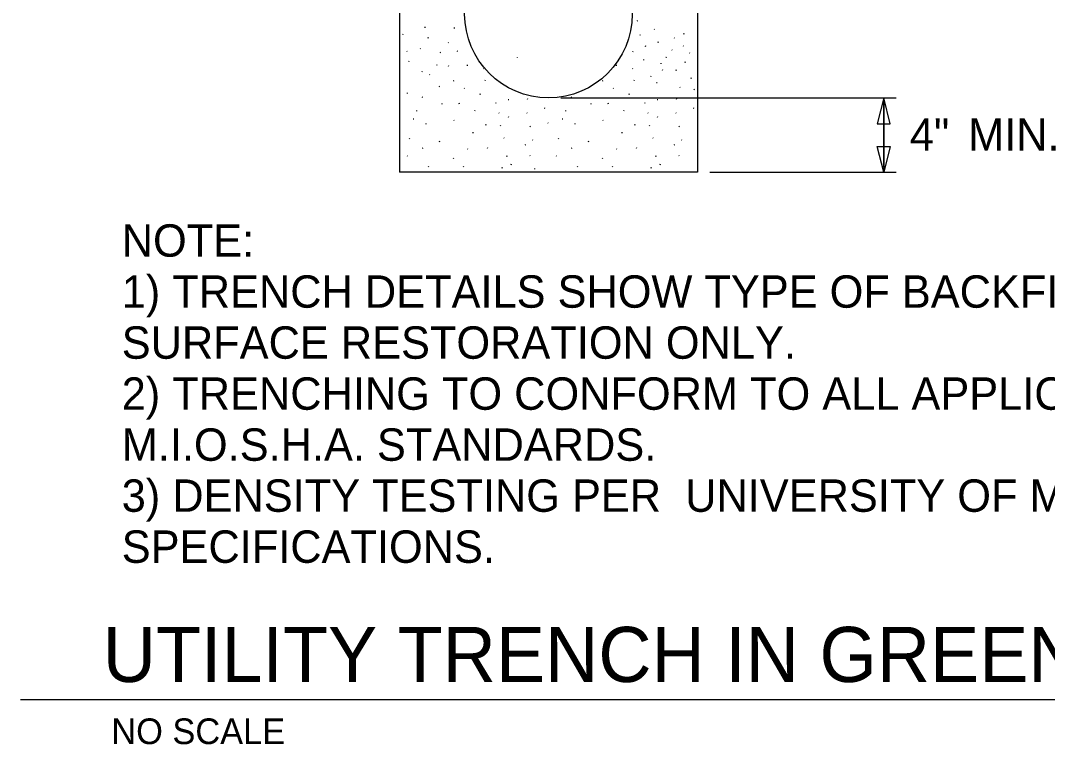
# Model space of a CAD drawing. Extents: x 9886.8 to 9948.5, y 10012 to 10070.9.
# Drawn here: x 9887.19 to 9920.27, y 10013.14 to 10036.46 of the extents above; entities that cross this region are included whole.
import ezdxf

# ---------------------------------------------------------------- set-up
doc = ezdxf.new("R2010")
doc.units = 0
for name, color, linetype in [('Default', 7, 'Continuous'), ('G-ANNO-TEXT', 7, 'Continuous'), ('G-ANNO-TTXT', 7, 'Continuous'), ('G-DETL-OTLN', 7, 'Continuous'), ('G-DETL-PATT', 7, 'Continuous')]:
    doc.layers.add(name, color=color, linetype=linetype)

# ---------------------------------------------------------------- blocks, each defined once
blk = doc.blocks.new('TERARR')
at = {"layer": 'Default'}
blk.add_lwpolyline([(-0.667, 0.167), (0, 0), (-0.667, -0.167)], close=True, dxfattribs=at)

msp = doc.modelspace()

# ---------------------------------------------------------------- linework, layer by layer
at = {"layer": 'Default'}
for p, q in [((9903.188, 10035.279), (9903.193, 10035.273)), ((9902.114, 10034.907), (9902.102, 10034.92)), ((9909.012, 10034.799), (9909.012, 10034.799)), ((9900.149, 10033.979), (9900.136, 10033.991)), ((9904.949, 10033.979), (9904.936, 10033.991)), ((9887.192, 10014.582), (9918.456, 10014.582))]:
    msp.add_line(p, q, dxfattribs=at)
at = {"layer": 'G-ANNO-TEXT'}
for p, q in [((9904.599, 10033.972), (9915.399, 10033.972)), ((9914.999, 10033.972), (9914.999, 10031.572)), ((9914.999, 10031.753), (9914.999, 10033.972)), ((9909.399, 10031.572), (9915.399, 10031.572)), ((9887.192, 10014.582), (9930.582, 10014.582))]:
    msp.add_line(p, q, dxfattribs=at)
at = {"layer": 'G-DETL-OTLN'}
for p, q in [((9899.399, 10039.372), (9899.399, 10031.572)), ((9908.999, 10039.372), (9908.999, 10031.572)), ((9908.999, 10031.572), (9899.399, 10031.572))]:
    msp.add_line(p, q, dxfattribs=at)
msp.add_circle((9904.199, 10036.672), 2.7, dxfattribs=at)
at = {"layer": 'G-DETL-PATT'}
for p, q in [((9900.237, 10036.24), (9900.211, 10036.235)), ((9901.179, 10036.217), (9901.153, 10036.212)), ((9907.072, 10036.449), (9907.047, 10036.444)), ((9907.612, 10036.168), (9907.6, 10036.18)), ((9899.513, 10036.01), (9899.522, 10036.035)), ((9900.33, 10035.904), (9900.304, 10035.898)), ((9907.151, 10035.987), (9907.16, 10036.012)), ((9908.263, 10035.896), (9908.25, 10035.908)), ((9908.569, 10036.032), (9908.543, 10036.026)), ((9900.075, 10035.546), (9900.063, 10035.559)), ((9900.975, 10035.746), (9900.963, 10035.758)), ((9907.326, 10035.627), (9907.334, 10035.652)), ((9907.734, 10035.759), (9907.742, 10035.784)), ((9908.188, 10035.509), (9908.175, 10035.522)), ((9908.55, 10035.634), (9908.538, 10035.646)), ((9899.65, 10035.459), (9899.638, 10035.472)), ((9899.7, 10035.137), (9899.708, 10035.162)), ((9900.725, 10035.434), (9900.7, 10035.422)), ((9901.275, 10035.459), (9901.263, 10035.472)), ((9906.919, 10035.453), (9906.927, 10035.478)), ((9907.268, 10035.183), (9907.277, 10035.208)), ((9907.978, 10035.284), (9907.988, 10035.279)), ((9907.988, 10035.279), (9907.993, 10035.273)), ((9908.75, 10035.409), (9908.738, 10035.422)), ((9900.13, 10034.808), (9900.138, 10034.833)), ((9900.607, 10035.021), (9900.615, 10035.045)), ((9900.979, 10034.994), (9900.987, 10035.018)), ((9901.598, 10035.015), (9901.572, 10035.009)), ((9906.398, 10035.015), (9906.372, 10035.009)), ((9906.914, 10034.907), (9906.902, 10034.92)), ((9907.827, 10035.067), (9907.835, 10035.092)), ((9907.873, 10034.858), (9907.881, 10034.883)), ((9908.311, 10034.854), (9908.319, 10034.879)), ((9908.602, 10035.113), (9908.61, 10035.138)), ((9900.381, 10034.71), (9900.369, 10034.723)), ((9901.156, 10034.516), (9901.13, 10034.51)), ((9902.165, 10034.529), (9902.174, 10034.554)), ((9905.956, 10034.516), (9905.93, 10034.51)), ((9906.965, 10034.529), (9906.974, 10034.554)), ((9907.5, 10034.657), (9907.509, 10034.682)), ((9908.799, 10034.599), (9908.808, 10034.624)), ((9900.695, 10034.327), (9900.683, 10034.34)), ((9901.498, 10034.269), (9901.485, 10034.282)), ((9906.298, 10034.269), (9906.285, 10034.282)), ((9907.7, 10034.458), (9907.675, 10034.452)), ((9908.446, 10034.304), (9908.433, 10034.316)), ((9908.899, 10034.234), (9908.887, 10034.247)), ((9899.653, 10034.111), (9899.661, 10034.136)), ((9902.005, 10034.086), (9901.979, 10034.081)), ((9902.924, 10033.912), (9902.898, 10033.907)), ((9903.522, 10033.926), (9903.531, 10033.951)), ((9906.805, 10034.086), (9906.779, 10034.081)), ((9907.724, 10033.912), (9907.698, 10033.907)), ((9908.322, 10033.926), (9908.331, 10033.951)), ((9899.955, 10033.543), (9899.964, 10033.568)), ((9900.77, 10033.763), (9900.778, 10033.788)), ((9901.33, 10033.785), (9901.304, 10033.779)), ((9901.828, 10033.554), (9901.836, 10033.579)), ((9902.503, 10033.798), (9902.511, 10033.823)), ((9904.088, 10033.631), (9904.075, 10033.643)), ((9904.755, 10033.543), (9904.764, 10033.568)), ((9905.57, 10033.763), (9905.578, 10033.788)), ((9906.13, 10033.785), (9906.104, 10033.779)), ((9906.628, 10033.554), (9906.636, 10033.579)), ((9907.303, 10033.798), (9907.311, 10033.823)), ((9908.888, 10033.631), (9908.875, 10033.643)), ((9899.864, 10033.286), (9899.839, 10033.28)), ((9901.161, 10033.236), (9901.148, 10033.249)), ((9902.615, 10033.48), (9902.602, 10033.492)), ((9902.91, 10033.349), (9902.919, 10033.374)), ((9903.513, 10033.478), (9903.5, 10033.49)), ((9904.192, 10033.155), (9904.18, 10033.167)), ((9904.664, 10033.286), (9904.639, 10033.28)), ((9905.961, 10033.236), (9905.948, 10033.249)), ((9907.415, 10033.48), (9907.402, 10033.492)), ((9907.71, 10033.349), (9907.719, 10033.374)), ((9908.313, 10033.478), (9908.3, 10033.49)), ((9900.265, 10033.12), (9900.252, 10033.133)), ((9901.77, 10032.835), (9901.778, 10032.86)), ((9902.191, 10033.1), (9902.165, 10033.094)), ((9902.654, 10033.067), (9902.662, 10033.092)), ((9903.625, 10033.054), (9903.6, 10033.041)), ((9905.065, 10033.12), (9905.052, 10033.133)), ((9906.57, 10032.835), (9906.578, 10032.86)), ((9906.991, 10033.1), (9906.965, 10033.094)), ((9907.454, 10033.067), (9907.462, 10033.092)), ((9908.425, 10033.054), (9908.4, 10033.041)), ((9899.723, 10032.649), (9899.731, 10032.674)), ((9900.688, 10032.556), (9900.696, 10032.581)), ((9902.777, 10032.667), (9902.765, 10032.68)), ((9903.7, 10032.605), (9903.688, 10032.617)), ((9904.523, 10032.649), (9904.531, 10032.674)), ((9905.488, 10032.556), (9905.496, 10032.581)), ((9907.577, 10032.667), (9907.565, 10032.68)), ((9908.5, 10032.605), (9908.488, 10032.617)), ((9900.155, 10032.346), (9900.13, 10032.34)), ((9901.603, 10032.319), (9901.59, 10032.332)), ((9902.235, 10032.347), (9902.244, 10032.372)), ((9903.463, 10032.455), (9903.438, 10032.442)), ((9904.955, 10032.346), (9904.93, 10032.34)), ((9906.403, 10032.319), (9906.39, 10032.332)), ((9907.035, 10032.347), (9907.044, 10032.372)), ((9908.263, 10032.455), (9908.238, 10032.442)), ((9899.66, 10032.087), (9899.648, 10032.1)), ((9901.142, 10032.011), (9901.15, 10032.036)), ((9902.866, 10032.09), (9902.84, 10032.085)), ((9903.613, 10032.106), (9903.6, 10032.118)), ((9904.46, 10032.087), (9904.448, 10032.1)), ((9905.942, 10032.011), (9905.95, 10032.036)), ((9907.666, 10032.09), (9907.64, 10032.085)), ((9908.413, 10032.106), (9908.4, 10032.118)), ((9900.339, 10031.744), (9900.347, 10031.769)), ((9901.467, 10031.744), (9901.476, 10031.769)), ((9902.712, 10031.709), (9902.72, 10031.734)), ((9903.003, 10031.817), (9903.012, 10031.842)), ((9903.755, 10031.675), (9903.763, 10031.699)), ((9905.139, 10031.744), (9905.147, 10031.769)), ((9906.267, 10031.744), (9906.276, 10031.769)), ((9907.512, 10031.709), (9907.52, 10031.734)), ((9907.803, 10031.817), (9907.812, 10031.842))]:
    msp.add_line(p, q, dxfattribs=at)

# ---------------------------------------------------------------- block references
at = {"layer": 'G-ANNO-TEXT', "xscale": 1.25}
for p, yscale, rotation in [((9914.999, 10033.972), -1.25, 90), ((9914.999, 10031.572), 1.25, -90)]:
    msp.add_blockref('TERARR', p, dxfattribs=dict(at, yscale=yscale, rotation=rotation))

# ---------------------------------------------------------------- texts
at = {"layer": 'G-ANNO-TEXT'}
for s, p in [('4"', (9915.841, 10032.265)), ('MIN.', (9917.717, 10032.265))]:
    msp.add_text(s, height=1.044, rotation=360, dxfattribs=at).set_placement(p)
for s, height, p in [('NOTE:', 1.044, (9890.452, 10028.852)), ('1) TRENCH DETAILS SHOW TYPE OF BACKFILL AND ', 1.044, (9890.452, 10027.208)), ('SURFACE RESTORATION ONLY.', 1.044, (9890.452, 10025.564)), ('2) TRENCHING TO CONFORM TO ALL APPLICABLE ', 1.044, (9890.452, 10023.92)), ('M.I.O.S.H.A. STANDARDS.', 1.044, (9890.452, 10022.276)), ('3) DENSITY TESTING PER  UNIVERSITY OF MICHIGAN ', 1.044, (9890.452, 10020.632)), ('SPECIFICATIONS.', 1.044, (9890.452, 10018.988)), ('NO SCALE', 0.828, (9890.117, 10013.147))]:
    msp.add_text(s, height=height, dxfattribs=at).set_placement(p)
at = {"layer": 'G-ANNO-TTXT'}
msp.add_text('UTILITY TRENCH IN GREEN BELT', height=1.776, dxfattribs=at).set_placement((9889.84, 10015.148))

doc.saveas('drawing.dxf')
